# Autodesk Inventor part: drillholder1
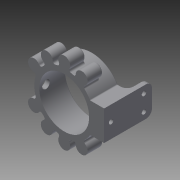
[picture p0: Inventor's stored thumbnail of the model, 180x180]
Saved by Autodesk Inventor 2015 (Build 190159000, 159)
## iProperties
Created: 2015-01
Part Number: drillholder1
Material: Generic
Document SubType Name: Modeling
Designer: jeroen
Density: 1 g/cm^3
Appearance: Default
Author: jeroen
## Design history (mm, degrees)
sketch "Sketch1"
  geometry: C1 r 25 at (0, 0); C2 r 30 at (0, 0); 1 further point
  constraints: 2 centre point, 2 coincident
  dimensions: "d0" = 50 diameter of C1; "d1" = 60 diameter of C2
extrude "Extrusion1" new body sketch "Sketch1" distance "d4" = 28; taper "d5" = 0 deg
chamfer "Chamfer1" distance "d6" = 28; stored, may be unused: second distance "d7" = 1.5, angle "d8" = 45 deg
sketch "Sketch2"
  geometry: L1 (25, 15)-(40, 15); L2 (40, 15)-(40, -15); L3 (40, -15)-(25, -15); C1 r 25 at (0, 0) reference; A1 r 29.155 centre (0, 0) between (25, -15) and (25, 15); 2 further points
  constraints: 6 end point, 2 point on circle, 1 centre point, 1 coincident, 1 horizontal, 1 horizontal alignment, 1 midpoint, 1 parallel, 1 perpendicular
  dimensions: "d9" = 30 distance of L1.end L2.end; "d10" = 15 distance of L1.start L1.end
extrude "Extrusion2" join sketch "Sketch2" stored distance "d11" = 28; taper "d12" = 0 deg
sketch "Sketch3"
  geometry: L1 (40, 15)-(40, -15) reference; L2 (40, 15)-(25.981, 15) reference; L3 (40, -15)-(35, -15); L4 (35, -15)-(35, 15); L5 (35, 15)-(40, 15); L6 (40, 15)-(40, -15); 1 further point
  constraints: 8 end point, 2 parallel, 1 horizontal, 1 perpendicular, 1 point on line
  dimensions: "d13" = 5 distance of L4.end L5.end
extrude "Extrusion3" join sketch "Sketch3" distance "d14" = 20; taper "d15" = 0 deg
fillet "Fillet1" dims "d16" = 6
fillet "Fillet2" dims "d17" = 6
sketch "Sketch4"
  geometry: L1 (-6, -14)-(-6, -6) reference; L2 (0, 0)-(18, 0) reference; C1 r 2.25 at (1, -8); C2 r 2.25 at (17, -8); 1 further point
  constraints: 2 centre point, 1 horizontal alignment
  dimensions: "d18" = 4.5 diameter of C1; "d19" = 4.5 diameter of C2; "d20" = 16 distance of C2.centre C1.centre; "d21" = 7 distance from line of C1.centre L1; "d22" = 8 distance from line of C2.centre L2
extrude "Extrusion4" cut sketch "Sketch4" stored distance "d23" = 20; taper "d24" = 0 deg
chamfer "Chamfer2" distance "d25" = 2.5; stored, may be unused: second distance "d26" = 2, angle "d27" = 45 deg
fillet "Fillet3" dims "d28" = 1
sketch "Sketch5"
  geometry: L1 (0, 0)-(30, 0) reference; C1 r 2.25 at (15, 7); 1 further point
  constraints: 1 centre point
  dimensions: "d29" = 4.5 diameter of C1; "d30" = 7 distance from line of C1.centre L1
extrude "Extrusion5" cut sketch "Sketch5" stored distance "d31" = 20; taper "d32" = 0 deg
chamfer "Chamfer3" distance "d33" = 2.5; stored, may be unused: second distance "d34" = 2, angle "d35" = 45 deg
workplane "Work Plane1"
sketch "Sketch6"
  geometry: C1 r 4 at (-14, -27); 2 further points
  constraints: 1 centre point, 1 other
  dimensions: "d62" = 8 diameter of C1
sketch "Sketch7" dims "d40" = 70
  geometry: C1 r 25 at (0, 0) reference; C2 r 4 at (0, 35); C3 r 6 at (0, 35); C4 r 6 at (17.5, 30.311); C5 r 4 at (17.5, 30.311); C6 r 6 at (30.311, 17.5); C7 r 4 at (30.311, 17.5); C8 r 6 at (35, 0); C9 r 4 at (35, 0); C10 r 6 at (30.311, -17.5); C11 r 4 at (30.311, -17.5); C12 r 6 at (17.5, -30.311); C13 r 4 at (17.5, -30.311); C14 r 6 at (0, -35); C15 r 4 at (0, -35); C16 r 6 at (-17.5, -30.311); C17 r 4 at (-17.5, -30.311); C18 r 6 at (-30.311, -17.5); C19 r 4 at (-30.311, -17.5); C20 r 6 at (-35, 0); C21 r 4 at (-35, 0); C22 r 6 at (-30.311, 17.5); C23 r 4 at (-30.311, 17.5); C24 r 6 at (-17.5, 30.311); C25 r 4 at (-17.5, 30.311); 13 further points
  constraints: 24 centre point, 15 coincident, 1 vertical alignment, 60 other
  dimensions: "d41" = 8 diameter of C2; "d42" = 12 diameter of C3; "d45" = 360 deg dimension on point (0, 0) C3.centre (derived)
extrude "Extrusion7" join sketch "Sketch7" distance "d47" = 15; taper "d48" = 0 deg
extrude "Extrusion8" cut sketch "Sketch8" distance "d57" = 13; taper "d58" = 0 deg
fillet "Fillet4" dims "d59" = 2
fillet "Fillet5" dims "d60" = 2
fillet "Fillet6" dims "d61" = 1
extrude "Extrusion9" cut sketch "Sketch6" distance "d63" = 20; taper "d64" = 0 deg
body "Solid1"
other parameters: "d36" = 75, "d49" = 8, "d50" = 8, "d51" = 8, "d52" = 8, "d53" = 8, "d54" = 8, "d55" = 8, "d56" = 8
